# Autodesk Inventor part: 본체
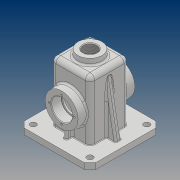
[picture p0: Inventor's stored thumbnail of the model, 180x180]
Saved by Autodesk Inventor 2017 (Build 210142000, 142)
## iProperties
Part Number: 본체
Material: 일반
Document SubType Name: Modeling
Designer: 20
Density: 1 g/cm^3
Appearance: 기본값
Mass: 293.223 g
Surface Area: 897.812 cm^2
Volume: 293.223 cm^3
Author: 20
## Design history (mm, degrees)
sketch "스케치1"
  geometry: L1 (-32.5, 32.5)-(32.5, 32.5); L2 (32.5, 32.5)-(32.5, -32.5); L3 (32.5, -32.5)-(-32.5, -32.5); L4 (-32.5, -32.5)-(-32.5, 32.5); L5 (-32.5, 32.5)-(32.5, -32.5); L6 (32.5, 32.5)-(-32.5, -32.5); 1 further point
  constraints: 12 end point, 2 midpoint, 2 parallel, 1 horizontal, 1 perpendicular
  dimensions: "d0" = 65 distance of L1.start L1.end; "d1" = 65 distance of L1.end L2.end
extrude "돌출1" new body sketch "스케치1" distance "d2" = 110; taper "d3" = 0 deg
fillet "모깎기1" dims "d6" = 8
fillet "모깎기2" dims "d7" = 8
feature "쉘1" dims "d8" = 5
sketch "스케치3"
  geometry: L1 (-60, -60)-(60, -60); L2 (60, -60)-(60, 60); L3 (60, 60)-(-60, 60); L4 (-60, 60)-(-60, -60); L5 (-60, -60)-(60, 60); L6 (60, -60)-(-60, 60); L7 (-27.5, -24.5)-(-27.5, 24.5) reference; L8 (-24.5, 27.5)-(24.5, 27.5) reference; L9 (27.5, 24.5)-(27.5, -24.5) reference; L10 (24.5, -27.5)-(-24.5, -27.5) reference; A1 r 3 centre (-24.5, 24.5) between (-24.5, 27.5) and (-27.5, 24.5) reference; A2 r 3 centre (24.5, 24.5) between (27.5, 24.5) and (24.5, 27.5) reference; A3 r 3 centre (24.5, -24.5) between (24.5, -27.5) and (27.5, -24.5) reference; A4 r 3 centre (-24.5, -24.5) between (-27.5, -24.5) and (-24.5, -27.5) reference; 1 further point
  constraints: 12 end point, 2 midpoint, 2 parallel, 1 horizontal, 1 perpendicular
  dimensions: "d9" = 120 distance of L3.end L1.start; "d10" = 120 distance of L2.end L3.end
extrude "돌출2" join sketch "스케치3" distance "d11" = 10; taper "d12" = 0 deg
sketch "스케치4"
  geometry: L1 (84.5, -102)-(-35.5, -102) reference; C1 r 27.5 at (24.5, -47); 2 further points
  constraints: 1 centre point, 1 midpoint, 1 vertical alignment
  dimensions: "d13" = 55 diameter of C1; "d14" = 55 distance from line of L1 C1.centre
extrude "돌출3" join sketch "스케치4" distance "d15" = 15; taper "d16" = 0 deg
sketch "스케치5" dims "d17" = 42
  geometry: L1 (60, -55)-(-60, -55) reference; A1 r 27.5 centre (0, 0) between (24.5, -12.49) and (24.5, 12.49) reference; 4 further points
  constraints: 2 vertical alignment, 1 coincident, 1 midpoint, 2 other
hole "구멍1" sketch "스케치5" at (0, 21) diameter "d18" = 3.242; stored, may be unused: countersink angle "d22" = 90 deg, drill point angle "d24" = 118 deg; dims "d19" = 8, "d20" = 4, "d21" = 2, "d23" = 10
sketch "스케치6"
  geometry: C1 r 17.5 at (0, 0); A1 r 27.5 centre (0, 0) between (24.5, 12.49) and (-24.5, 12.49) reference; 1 further point
  constraints: 1 centre point, 1 coincident
  dimensions: "d28" = 35 diameter of C1
extrude "돌출4" cut sketch "스케치6" distance "d29" = 17; taper "d30" = 0 deg
sketch "스케치7"
  geometry: C1 r 17.5 at (0, 0) reference; C2 r 15 at (0, 0); 1 further point
  constraints: 1 centre point, 1 coincident
  dimensions: "d31" = 30 diameter of C2
extrude "돌출5" cut sketch "스케치7" distance "d32" = 3; taper "d33" = 0 deg
sketch "스케치8"
  geometry: L1 (-60, 10)-(60, 10) reference; L2 (-48, 10)-(-38.644, 63.061); L3 (-60, 0)-(-60, 10) reference; 1 further point
  constraints: 2 end point, 1 point on line
  dimensions: "d34" = 12 distance from line of L3 L2.start; "d35" = 10 deg angle of L3 L2; "d36" = 53.06146 vertical distance of L2.start L2.end
feature "리브1" sketch "스케치8" dims "d37" = 1, "d38" = 10, "d39" = 0, "d40" = 0, "d41" = 1, "d42" = 1
node "작업 평면2"
sketch "스케치13"
  geometry: C1 r 20 at (0, 0); 1 further point
  constraints: 1 centre point, 1 coincident
  dimensions: "d96" = 40 diameter of C1
extrude "돌출8" join sketch "스케치13" stored distance "d97" = 10; taper "d98" = 5 deg
hole "구멍3" diameter "d101" = 22.835; stored, may be unused: countersink angle "d105" = 90 deg, drill point angle "d107" = 0 deg; dims "d99" = 10, "d100" = 10, "d102" = 50, "d103" = 4, "d104" = 2, "d106" = 30
sketch "스케치10"
  geometry: L1 (60, 10)-(-60, 10) reference; L2 (-42.5, 10)-(-42.5, 22.135); L3 (-27.5, 0)-(-27.5, 102) reference; 1 further point
  constraints: 2 end point, 1 point on line, 1 vertical
  dimensions: "d55" = 15 distance between parallel lines of L3 L2; "d56" = 12.13511 distance of L2.start L2.end
feature "리브2" sketch "스케치10" dims "d57" = 1, "d58" = 6, "d59" = 0, "d60" = 0, "d61" = 1, "d62" = 1
chamfer "모따기1" distance "d63" = 10; stored, may be unused: second distance "d64" = 2, angle "d65" = 45 deg
sketch "스케치11"
  geometry: C1 r 5 at (47.5, 47.5); 1 further point
  constraints: 1 centre point
  dimensions: "d66" = 10 diameter of C1; "d67" = 47.5 horizontal distance of point (0, 0) C1.centre; "d68" = 47.5 horizontal distance of point (0, 0) C1.centre
extrude "돌출7" cut sketch "스케치11" distance "d69" = 10; taper "d70" = 0 deg
fillet "모깎기3" dims "d77" = 0.3
fillet "모깎기4" dims "d78" = 3
fillet "모깎기5" dims "d79" = 3
fillet "모깎기6" dims "d80" = 3
fillet "모깎기7" dims "d81" = 3
fillet "모깎기8" dims "d82" = 3
fillet "모깎기9" dims "d83" = 3
fillet "모깎기10" dims "d84" = 3
fillet "모깎기11" dims "d85" = 1
chamfer "모따기2" distance "d86" = 1; stored, may be unused: second distance "d87" = 2, angle "d88" = 45 deg
node "작업 평면1"
sketch "스케치12"
  geometry: L1 (57, 0)-(57, 91) reference; L2 (4.5, -18)-(44.5, -18) reference; 2 further points
  constraints: 1 other
  dimensions: "d91" = 32.5 distance from line of L1 point (24.5, 8); "d108" = 26 distance from line of L2 point (24.5, 8)
feature "엠보싱1" sketch "스케치12" dims "d8" = 5, "d93" = 0.5, "d94" = 0
fillet "모깎기13" dims "d109" = 3
chamfer "모따기3" distance "d110" = 1; stored, may be unused: second distance "d111" = 2, angle "d112" = 45 deg
node "솔리드1"
pattern_circular "원형 패턴1" dims angle "d26" = 360 deg
mirror "미러1"
mirror "미러2"
mirror "미러3"
pattern_linear "직사각형 패턴1" dims "d73" = 95, "d76" = 95
